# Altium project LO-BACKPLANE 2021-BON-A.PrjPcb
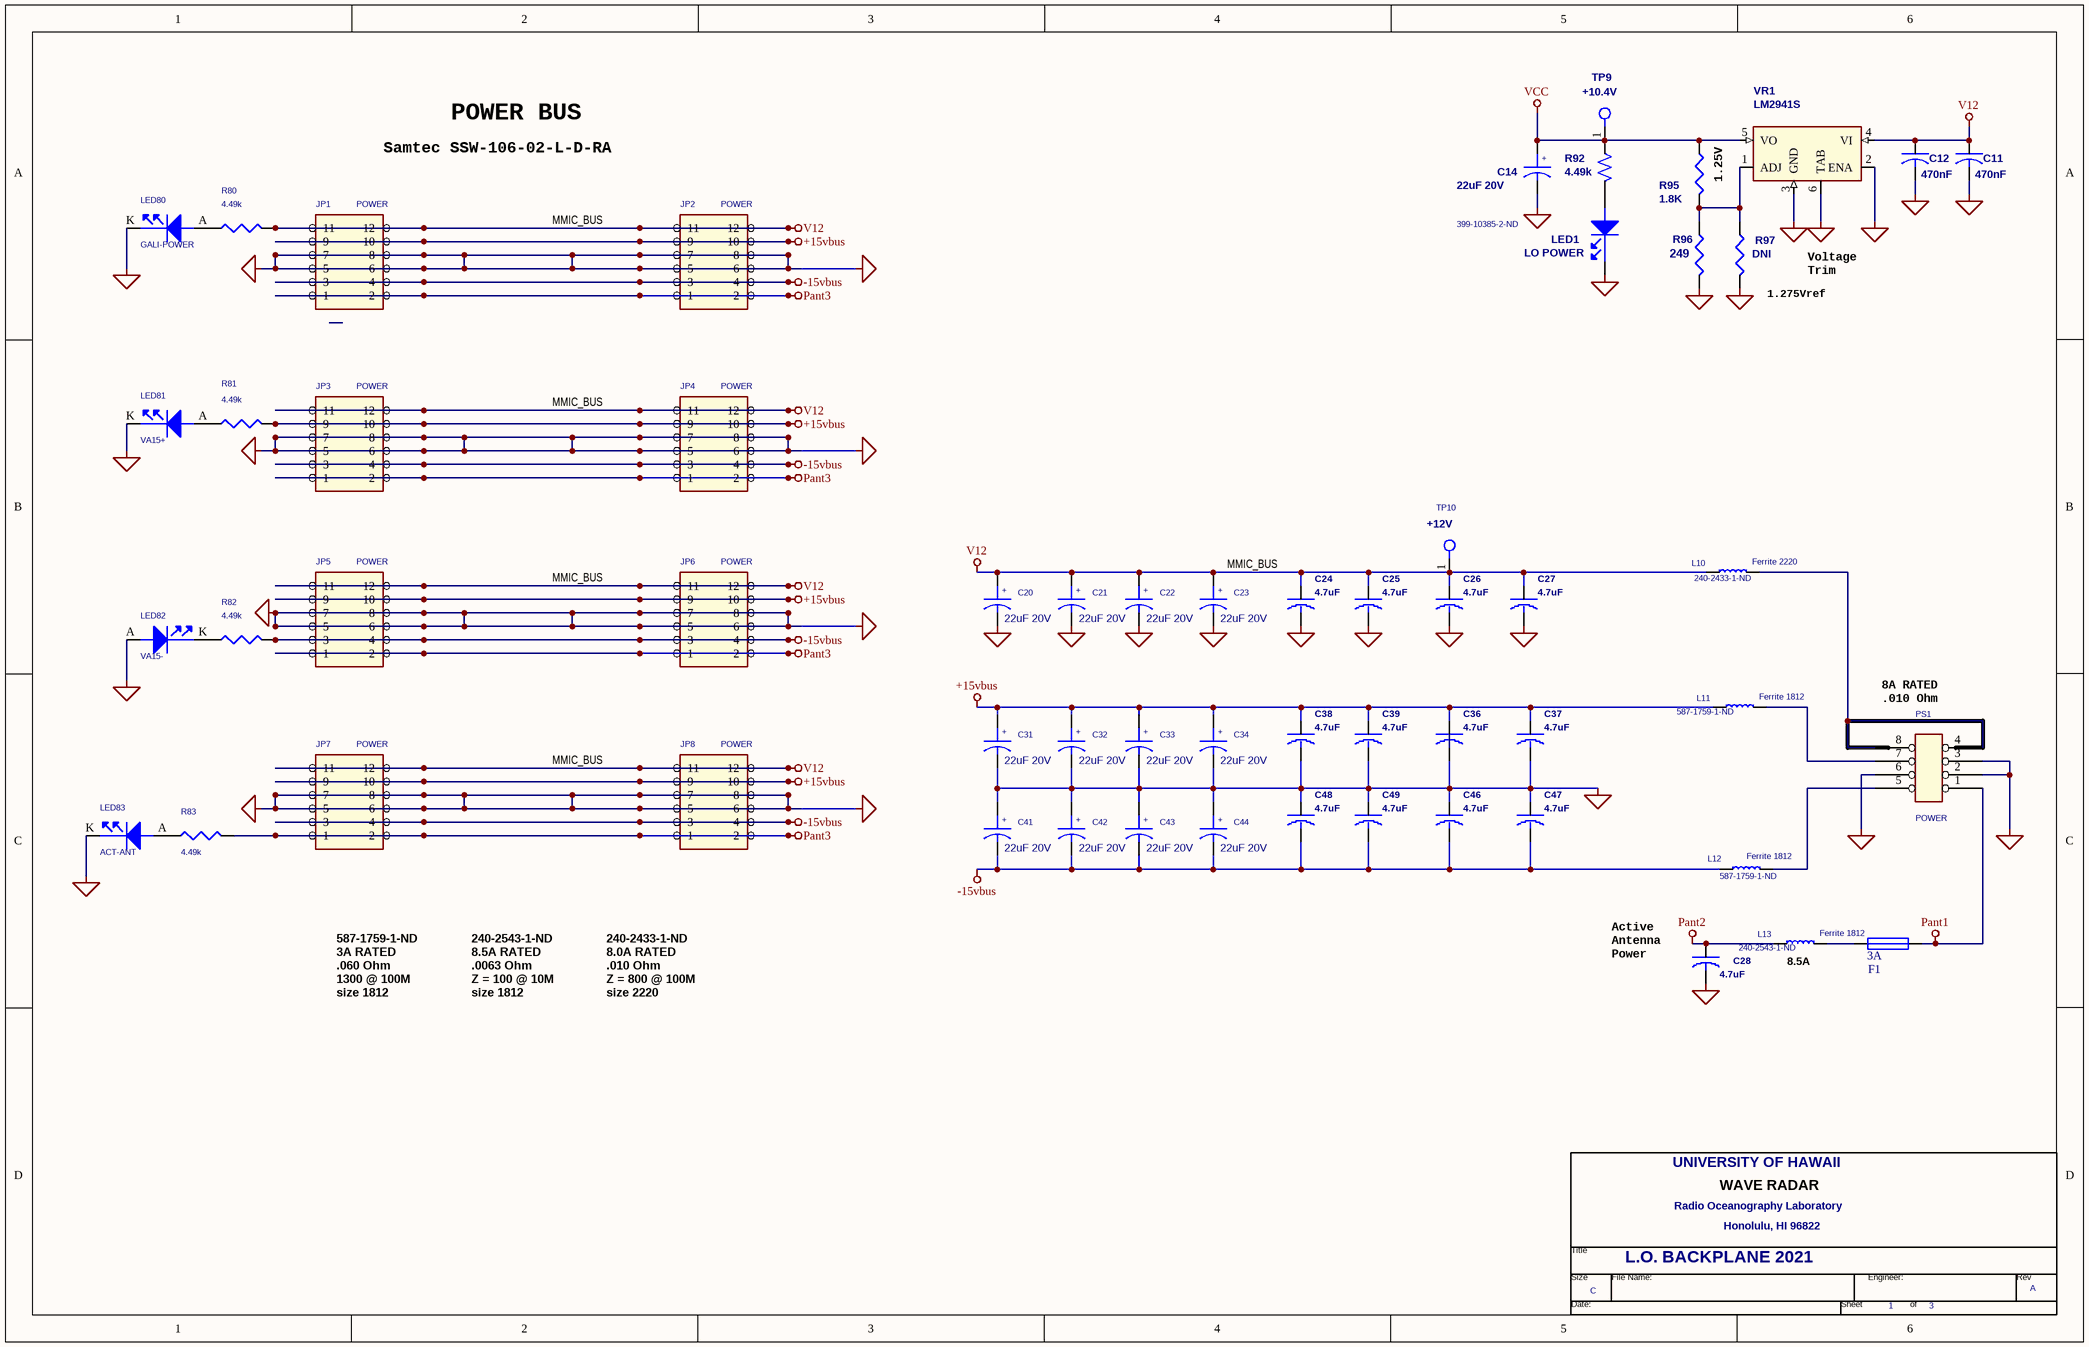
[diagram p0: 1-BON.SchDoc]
3 sheets, 162 parts. Net scope: global (net labels, ports and power ports of the same name join across sheets).
Board file: LO-BACKPLANE2021-BON.PcbDoc
Sheets:
  1-BON.SchDoc
  2-BON.SchDoc
  3-BON.SchDoc

## Sheet 1-BON.SchDoc
size OrCAD B; Organization: Altium Limited; Address1: L3, 12a Rodborough Rd; Address2: Frenchs Forest; Address3: NSW; Address4: Australia 2086

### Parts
(Parts that share a designator on the sheet are numbered #1, #2 ... from top to bottom, then left to right.)
*#1  Page Count: 3  Page Number: 1  Page Size: C  OrgAddr3: Honolulu, HI 96822  OrgAddr1: Radio Oceanography Laboratory  OrgName: UNIVERSITY OF HAWAII  Title: L.O. BACKPLANE 2021  RevCode: A  (hidden comment: HWRadar)  (graphical)
C11  470nF  [0612]
C12  470nF  [0612]
C14  22uF 20V  DK Stock: 399-10385-2-ND  [293D]
C20  22uF 20V  [293D]
C21  22uF 20V  [293D]
C22  22uF 20V  [293D]
C23  22uF 20V  [293D]
C24  4.7uF  [1210]
C25  4.7uF  [1210]
C26  4.7uF  [1210]
C27  4.7uF  [1210]
C28  4.7uF  [1210]
C31  22uF 20V  [293D]
C32  22uF 20V  [293D]
C33  22uF 20V  [293D]
C34  22uF 20V  [293D]
C36  4.7uF  [1210]
C37  4.7uF  [1210]
C38  4.7uF  [1210]
C39  4.7uF  [1210]
C41  22uF 20V  [293D]
C42  22uF 20V  [293D]
C43  22uF 20V  [293D]
C44  22uF 20V  [293D]
C46  4.7uF  [1210]
C47  4.7uF  [1210]
C48  4.7uF  [1210]
C49  4.7uF  [1210]
F1  3A  [0452 (Littlefuse)]
JP1  POWER  [SSW-106-02-G-D-RA]
JP2  POWER  [SSW-106-02-G-D-RA]
JP3  POWER  [SSW-106-02-G-D-RA]
JP4  POWER  [SSW-106-02-G-D-RA]
JP5  POWER  [SSW-106-02-G-D-RA]
JP6  POWER  [SSW-106-02-G-D-RA]
JP7  POWER  [SSW-106-02-G-D-RA]
JP8  POWER  [SSW-106-02-G-D-RA]
L10  Ferrite 2220  DK Stock: 240-2433-1-ND  [2220]
L11  Ferrite 1812  DK Stock: 587-1759-1-ND  [1812]
L12  Ferrite 1812  DK Stock: 587-1759-1-ND  [1812]
L13  Ferrite 1812  DK Stock: 240-2543-1-ND  [1812]
LED1  LO POWER  [1206D1]
LED80  GALI-POWER  [1206D1]
LED81  VA15+  [1206D1]
LED82  VA15-  [1206D1]
LED83  ACT-ANT  [1206D1]
PS1  POWER  [MFTJR2X4]
R80  4.49k  [R1206]
R81  4.49k  [R1206]
R82  4.49k  [R1206]
R83  4.49k  [R1206]
R92  4.49k  [R1206]
R95  1.8K  [R1206]
R96  249  [R1206]
R97  DNI  [R1206]
TP9  +10.4V  [61300111121]
TP10  +12V  [61300111121]
VR1  LM2941S  [TO263-5]

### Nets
+15vbus: C31.+ C32.+ C33.+ C34.+ C36.1 C37.1 C38.1 C39.1 JP1.9 JP1.10 JP2.9 JP2.10 JP3.9 JP3.10 JP4.9 JP4.10 JP5.9 JP5.10 JP6.9 JP6.10 JP7.9 JP7.10 JP8.9 JP8.10 L11.1 R81.2
-15vbus: C41.- C42.- C43.- C44.- C46.2 C47.2 C48.2 C49.2 JP1.3 JP1.4 JP2.3 JP2.4 JP3.3 JP3.4 JP4.3 JP4.4 JP5.3 JP5.4 JP6.3 JP6.4 JP7.3 JP7.4 JP8.3 JP8.4 L12.1 R82.2
GND: C11.2 C12.2 C14.- C20.- C21.- C22.- C23.- C24.2 C25.2 C26.2 C27.2 C28.2 C31.- C32.- C33.- C34.- C36.2 C37.2 C38.2 C39.2 C41.+ C42.+ C43.+ C44.+ C46.1 C47.1 C48.1 C49.1 JP1.5 JP1.6 JP1.7 JP1.8 JP2.5 JP2.6 JP2.7 JP2.8 JP3.5 JP3.6 JP3.7 JP3.8 JP4.5 JP4.6 JP4.7 JP4.8 JP5.5 JP5.6 JP5.7 JP5.8 JP6.5 JP6.6 JP6.7 JP6.8 JP7.5 JP7.6 JP7.7 JP7.8 JP8.5 JP8.6 JP8.7 JP8.8 LED1.K(CATHODE) LED80.K(CATHODE) LED81.K(CATHODE) LED82.A(ANODE) LED83.K(CATHODE) PS1.2 PS1.3 PS1.6 R96.2 R97.2 VR1.2(ENA) VR1.3(GND) VR1.6(TAB)
Pant1: F1.2 PS1.1
Pant2: C28.1 L13.1
Pant3: JP1.1 JP1.2 JP2.1 JP2.2 JP3.1 JP3.2 JP4.1 JP4.2 JP5.1 JP5.2 JP6.1 JP6.2 JP7.1 JP7.2 JP8.1 JP8.2 R83.2
V12: C11.1 C12.1 C20.+ C21.+ C22.+ C23.+ C24.1 C25.1 C26.1 C27.1 JP1.11 JP1.12 JP2.11 JP2.12 JP3.11 JP3.12 JP4.11 JP4.12 JP5.11 JP5.12 JP6.11 JP6.12 JP7.11 JP7.12 JP8.11 JP8.12 L10.1 R80.2 TP10.1(TP) VR1.4(VI)
VCC: C14.+ R92.1 R95.1 TP9.1(TP) VR1.5(VO)
NetF1_1: F1.1 L13.2
NetL10_2: L10.2 PS1.4 PS1.8
NetL11_2: L11.2 PS1.7
NetL12_2: L12.2 PS1.5
NetLED1_A: LED1.A(ANODE) R92.2
NetLED80_A: LED80.A(ANODE) R80.1
NetLED81_A: LED81.A(ANODE) R81.1
NetLED82_K: LED82.K(CATHODE) R82.1
NetLED83_A: LED83.A(ANODE) R83.1
NetR95_2: R95.2 R96.1 R97.1 VR1.1(ADJ)

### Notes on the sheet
- Samtec SSW-106-02-L-D-RA
- POWER BUS
- (near R95) 1.25V
- MMIC_BUS
- Voltage
  Trim
- (near R97) 1.275Vref
- (near C23) MMIC_BUS
- (near PS1) 8A RATED
  .010 Ohm
- (near L13) 8.5A
- 587-1759-1-ND
  3A RATED
  .060 Ohm
  1300 @ 100M
  size 1812
- 240-2543-1-ND
  8.5A RATED
  .0063 Ohm
  Z = 100 @ 10M
  size 1812
- 240-2433-1-ND
  8.0A RATED
  .010 Ohm
  Z = 800 @ 100M
  size 2220
- (near C28) Active
  Antenna
  Power

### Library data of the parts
*#1 = HWRadar: OrgAddr2: 2525 Correa Road; Engineer:: <ENG>
C11 C12 = CAP: MFR PART: C1632X7R1E474M115AC; MFR: TDK; DK Stock: 445-14304-1-ND
C14 = CAPACITOR POL: MFR PART: T495D226M020ATE225; MFR: Kemet
C20-C23 C31-C34 C41-C44 = CAPACITOR POL: MFR PART: T495D226M020ATE225; MFR: Kemet; DK Stock: 399-10385-1-ND
C24-C28 C36-C39 C46-C49 = C1206: MFR PART: C3225X7R1E475K200AA; MFR: TDK Corporation; DK Stock: 445-1433-2-ND
F1 = FUSE1: Fuse
JP1-JP8 = HEADER 6X2: MFR: Samtec Inc.; DK Stock: SAM1215-06-ND
L10 = IND: MFR PART: HR2220V801R-10; MFR: Laird
L11 L12 = IND: MFR PART: FBMH4532HM132-T; MFR: Taiyo Yuden
L13 = IND: MFR PART: HI1812V101R-10; MFR: Laird
LED1 = LED_1: MFR PART: APTL3216CGCK; MFR: Kingbright; DK Stock: 754-1162-1-ND
LED80 = LED_0: MFR PART: APTD3216SURCK; MFR: Kingbright; DK Stock: 754-1159-1-ND
LED81 = LED_0: MFR PART: APTD3216SECK; MFR: Kingbright; DK Stock: 754-1156-1-ND
LED82 = LED_0: MFR PART: APTD3216SYCK; MFR: Kingbright; DK Stock: 754-1160-1-ND
LED83 = LED_0: MFR PART: APTD3216QBC/D; MFR: Kingbright; DK Stock: 754-1442-1-ND
PS1 = HEADER 4X2_0: MFR PART: 0039281083; MFR: M olex; DK Stock: WM3803-ND
R80-R83 = RESISTOR: MFR PART: RC1206FR-072K49L; MFR: Yageo; DK Stock: 311-2.49KFRCT-ND
R92 = RES1206: MFR PART: RC1206FR-072K49L; MFR: Yageo; DK Stock: 311-4.99KFRCT-ND
R95 = RESISTOR: MFR PART: RC1206FR-071K8L; MFR: Yageo; DK Stock: 311-1.80kFRCT-ND
R96 = RESISTOR: MFR PART: RC1206FR-07249RL; MFR: Yageo; DK Stock: 311-249FRCT-ND
R97 = RESISTOR: MFR PART: ns; DK Stock: OMIT
TP9 = TP_0: MFR PART: ns; DK Stock: n/s
TP10 = TP_0: DK Stock: n/s
VR1 = LM7805_0: MFR PART: LM2941SX; MFR: TI; DK Stock: LM2941SXCT-ND

## Sheet 2-BON.SchDoc
size OrCAD B; Organization: Altium Limited; Address1: L3, 12a Rodborough Rd; Address2: Frenchs Forest; Address3: NSW; Address4: Australia 2086
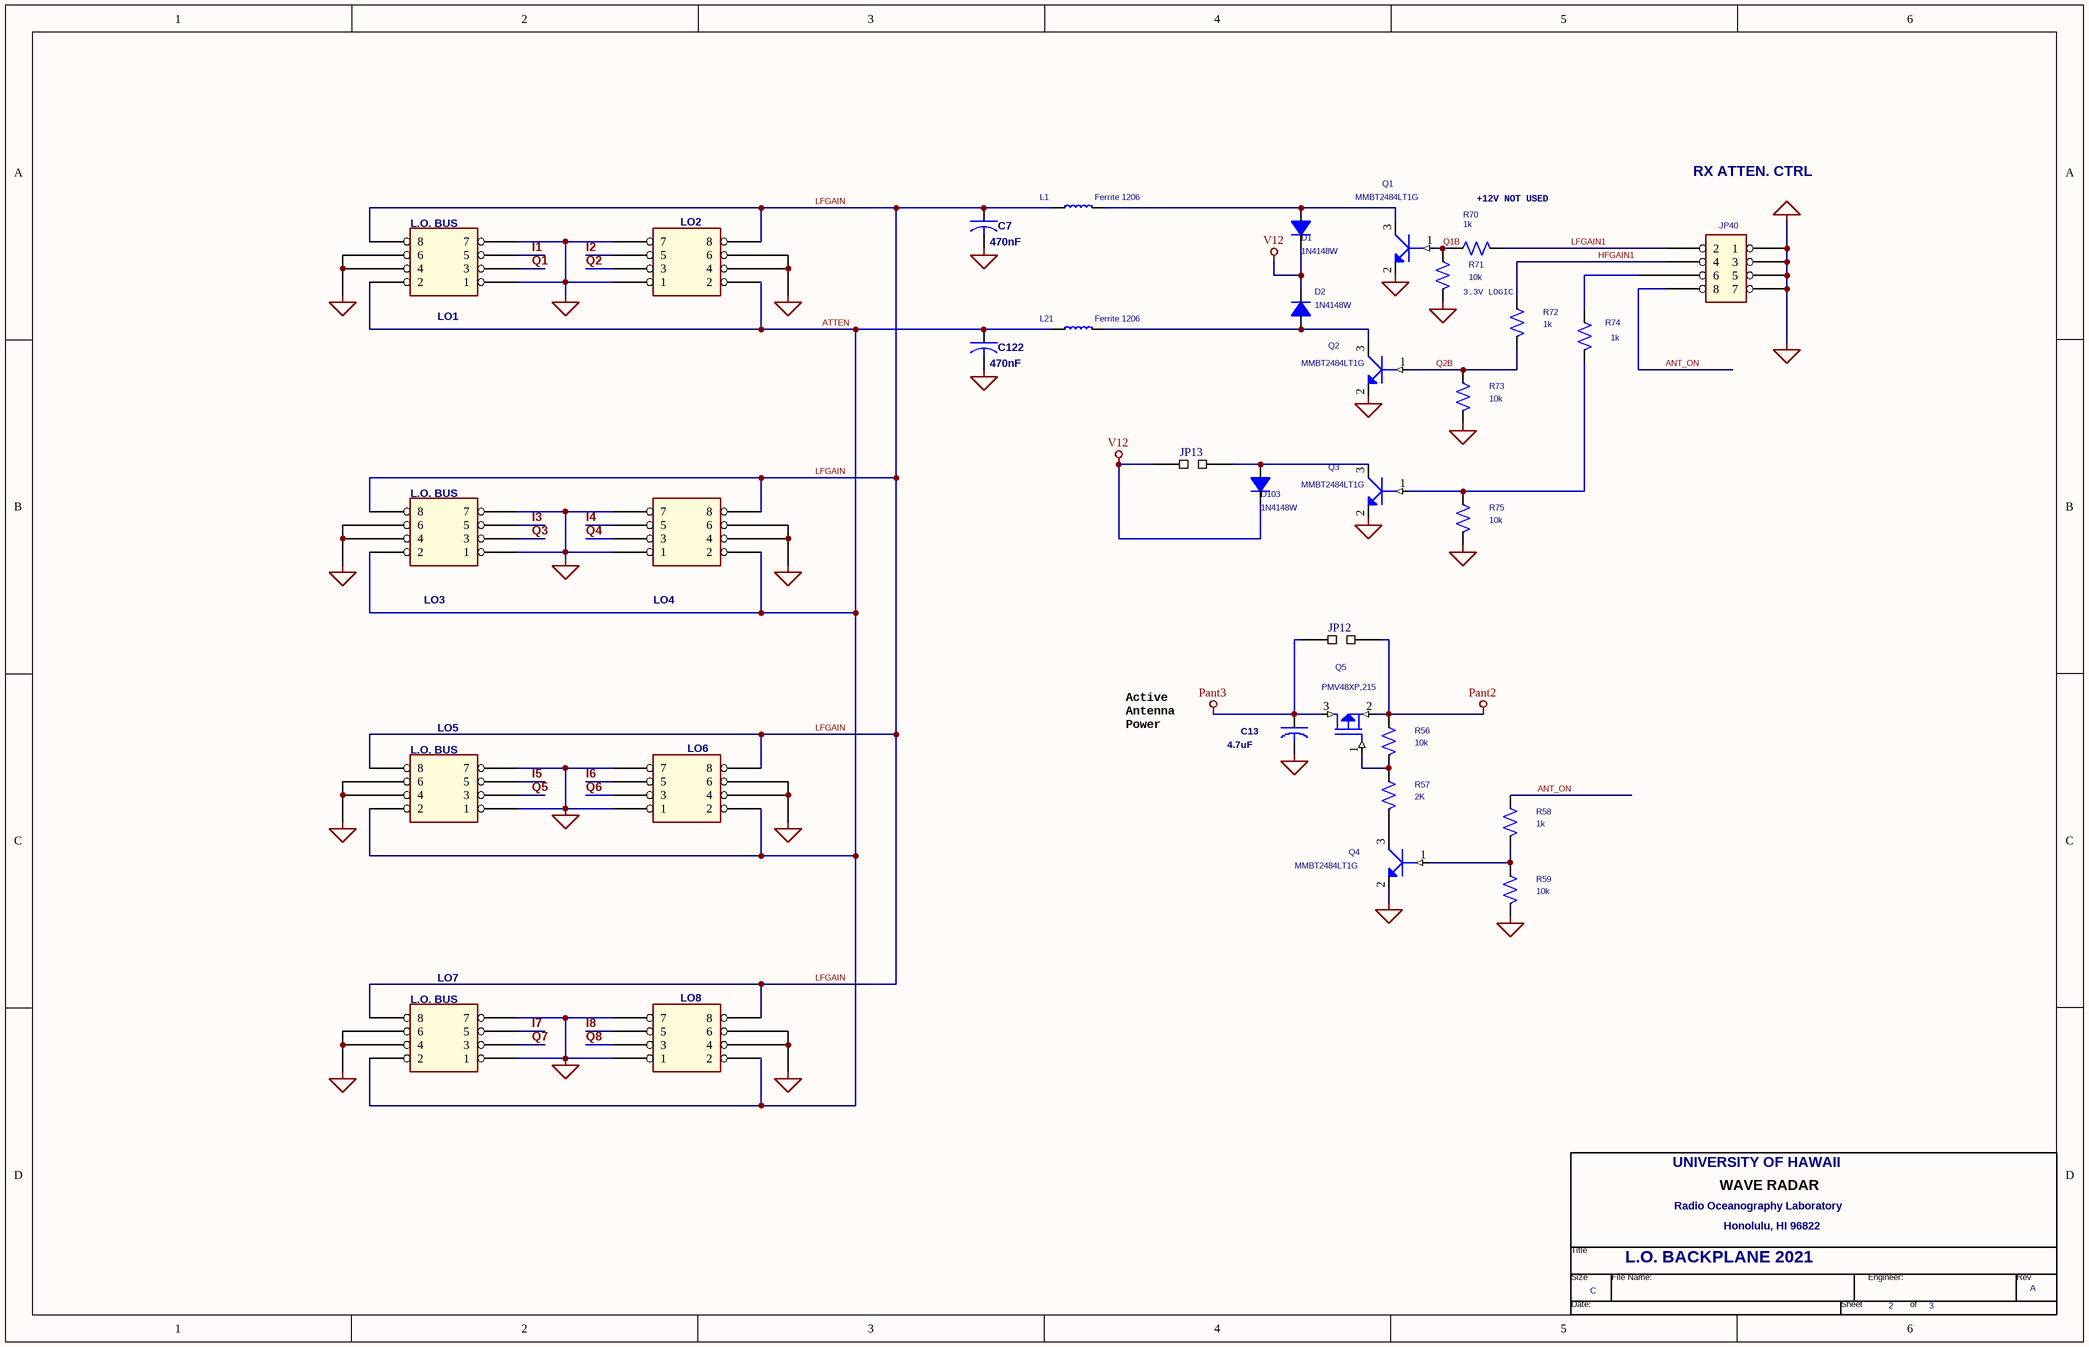
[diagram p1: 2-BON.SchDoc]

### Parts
(Parts that share a designator on the sheet are numbered #1, #2 ... from top to bottom, then left to right.)
*#2  Page Count: 3  Page Number: 2  Page Size: C  OrgAddr3: Honolulu, HI 96822  OrgAddr1: Radio Oceanography Laboratory  OrgName: UNIVERSITY OF HAWAII  Title: L.O. BACKPLANE 2021  RevCode: A  (hidden comment: HWRadar)  (graphical)
C7  470nF  [0612]
C13  4.7uF  [1206]
C122  470nF  [0612]
D1  1N4148W  [SOD123]
D2  1N4148W  [SOD123]
D103  1N4148W  [SOD123]
JP12  (no value)  [2X2.54]
JP13  (no value)  [2X2.54]
JP40  RX ATTEN. CTRL  [2MM4X2SHRD]
L1  Ferrite 1206  [1206]
L21  Ferrite 1206  [1206]
LO1  L.O. BUS  [SSW-104-02-G-D-RA]
LO2  L.O. BUS  [SSW-104-02-G-D-RA]  (value not drawn)
LO3  L.O. BUS  [SSW-104-02-G-D-RA]
LO4  L.O. BUS  [SSW-104-02-G-D-RA]  (value not drawn)
LO5  L.O. BUS  [SSW-104-02-G-D-RA]
LO6  L.O. BUS  [SSW-104-02-G-D-RA]  (value not drawn)
LO7  L.O. BUS  [SSW-104-02-G-D-RA]
LO8  L.O. BUS  [SSW-104-02-G-D-RA]  (value not drawn)
Q1  MMBT2484LT1G  [SOT23]
Q2  MMBT2484LT1G  [SOT23]
Q3  MMBT2484LT1G  [SOT23]
Q4  MMBT2484LT1G  [SOT23]
Q5  PMV48XP,215  [SOT23]
R56  10k  [1206]
R57  2K  [1206]
R58  1k  [1206]
R59  10k  [1206]
R70  1k  [1206]
R71  10k  [1206]
R72  1k  [1206]
R73  10k  [1206]
R74  1k  [1206]
R75  10k  [1206]

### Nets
GND: C7.2 C13.2 C122.2 JP40.1 JP40.3 JP40.5 JP40.7 LO1.1 LO1.4 LO1.6 LO1.7 LO2.1 LO2.4 LO2.6 LO2.7 LO3.1 LO3.4 LO3.6 LO3.7 LO4.1 LO4.4 LO4.6 LO4.7 LO5.1 LO5.4 LO5.6 LO5.7 LO6.1 LO6.4 LO6.6 LO6.7 LO7.1 LO7.4 LO7.6 LO7.7 LO8.1 LO8.4 LO8.6 LO8.7 Q1.2(EMITTER) Q2.2(EMITTER) Q3.2(EMITTER) Q4.2(EMITTER) R59.2 R71.2 R73.2 R75.2
Pant2: JP12.2 Q5.2(SOURCE) R56.1
Pant3: C13.1 JP12.1 Q5.3(DRAIN)
V12: D1.K(CATH) D2.K(CATH) D103.K(CATH) JP13.1
ANT_ON: JP40.8 R58.1
ATTEN: C122.1 L21.1 LO1.2 LO2.2 LO3.2 LO4.2 LO5.2 LO6.2 LO7.2 LO8.2
HFGAIN1: JP40.4 R72.1
I1: LO1.5
I2: LO2.5
I3: LO3.5
I4: LO4.5
I5: LO5.5
I6: LO6.5
I7: LO7.5
I8: LO8.5
LFGAIN: C7.1 L1.1 LO1.8 LO2.8 LO3.8 LO4.8 LO5.8 LO6.8 LO7.8 LO8.8
LFGAIN1: JP40.2 R70.2
Q1: LO1.3
Q1B: Q1.1(BASE) R70.1 R71.1
Q2: LO2.3
Q2B: Q2.1(BASE) R72.2 R73.1
Q3: LO3.3
Q4: LO4.3
Q5: LO5.3
Q6: LO6.3
Q7: LO7.3
Q8: LO8.3
NetD1_A: D1.A(ANOD) L1.2 Q1.3(COLLECTOR)
NetD2_A: D2.A(ANOD) L21.2 Q2.3(COLLECTOR)
NetD103_A: D103.A(ANOD) JP13.2 Q3.3(COLLECTOR)
NetJP40_6: JP40.6 R74.1
NetQ3_1: Q3.1(BASE) R74.2 R75.1
NetQ4_1: Q4.1(BASE) R58.2 R59.1
NetQ4_3: Q4.3(COLLECTOR) R57.2
NetQ5_1: Q5.1(GATE) R56.2 R57.1

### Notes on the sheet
- +12V NOT USED
- 3.3V LOGIC
- Active
  Antenna
  Power

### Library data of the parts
*#2 = HWRadar: as *#1 on sheet 1-BON
C7 C122 = CAP: as C11 on sheet 1-BON
C13 = C1206: MFR: Taiyo Yuden; DK Stock: 587-1389-1-ND
D1 D2 D103 = DIODE2: MFR: Micro Commercial; MFR PART: 1N4148W-TP; DK Stock: 1N4148WTPMSCT-ND
JP12 JP13 = STRAP
JP40 = HEADER 4X2_1: MFR: 3M; MFR PART: 159208-6012
L1 L21 = IND: MFR: Taiyo Yuden; MFR PART: HZ1206D102R-10
LO1-LO8 = HEADER 4X2: MFR: Samtec; DK Stock: SAM1045-04-ND
Q1-Q4 = NPN_0: DK Stock: MMBT2484LT1GOSCT-ND
Q5 = MOSFET P_0: DK Stock: 568-7579-1-ND
R56 R57 = RES1206: MFR: Yageo
R58 R59 R70-R75 = RES1206_Dup1: MFR: Yageo

## Sheet 3-BON.SchDoc
size OrCAD B; Organization: Altium Limited; Address1: L3, 12a Rodborough Rd; Address2: Frenchs Forest; Address3: NSW; Address4: Australia 2086
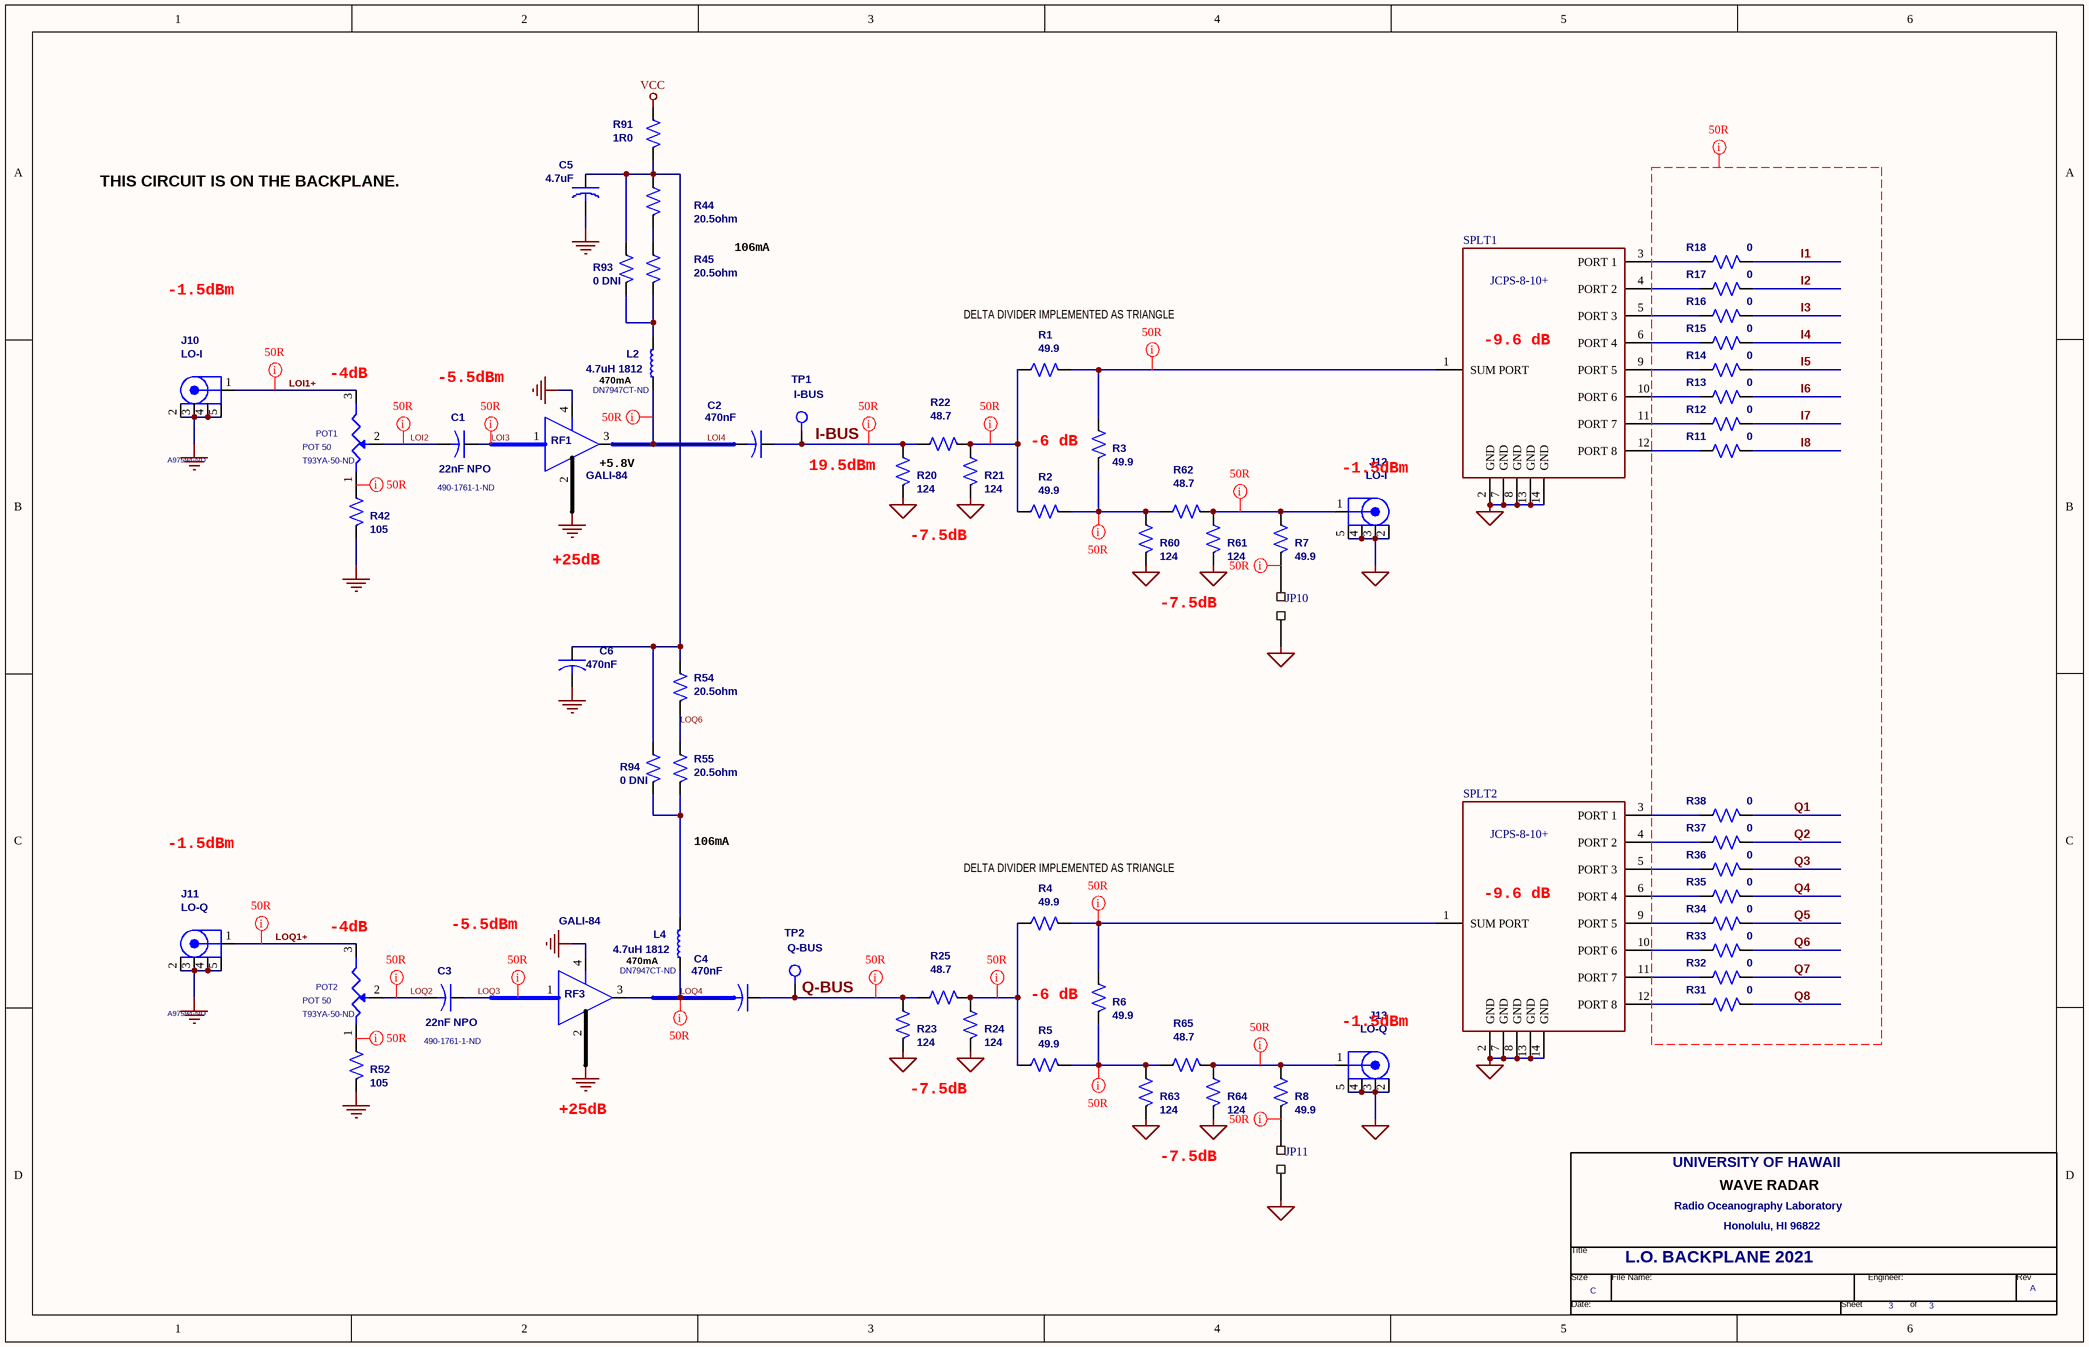
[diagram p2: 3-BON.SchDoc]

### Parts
(Parts that share a designator on the sheet are numbered #1, #2 ... from top to bottom, then left to right.)
*#3  Page Count: 3  Page Size: C  OrgAddr3: Honolulu, HI 96822  OrgAddr1: Radio Oceanography Laboratory  OrgName: UNIVERSITY OF HAWAII  Title: L.O. BACKPLANE 2021  RevCode: A  (hidden comment: HWRadar)  (graphical)
C1  22nF NPO  DK Stock: 490-1761-1-ND  [C1206]
C2  470nF  [0612]
C3  22nF NPO  DK Stock: 490-1761-1-ND  [C1206]
C4  470nF  [0612]
C5  4.7uF  [1210]
C6  470nF  [0612]
J10  LO-I  DK Stock: A97594-ND  [MCX-J-P-H-ST-TH1]
J11  LO-Q  DK Stock: A97594-ND  [MCX-J-P-H-ST-TH1]
J12  LO-I  [MCX-J-P-H-ST-TH1]
J13  LO-Q  [MCX-J-P-H-ST-TH1]
JP10  (no value)  [2X2.54]
JP11  (no value)  [2X2.54]
L2  4.7uH 1812  DK Stock: DN7947CT-ND  [1812]
L4  4.7uH 1812  DK Stock: DN7947CT-ND  [1812]
POT1  POT 50  DK Stock: T93YA-50-ND  [t93ya]
POT2  POT 50  DK Stock: T93YA-50-ND  [t93ya]
R1  49.9  [R1206]
R2  49.9  [R1206]
R3  49.9  [R1206]
R4  49.9  [R1206]
R5  49.9  [R1206]
R6  49.9  [R1206]
R7  49.9  [R1206]
R8  49.9  [R1206]
R11  0  [R1206]
R12  0  [R1206]
R13  0  [R1206]
R14  0  [R1206]
R15  0  [R1206]
R16  0  [R1206]
R17  0  [R1206]
R18  0  [R1206]
R20  124  [R1206]
R21  124  [R1206]
R22  48.7  [R1206]
R23  124  [R1206]
R24  124  [R1206]
R25  48.7  [R1206]
R31  0  [R1206]
R32  0  [R1206]
R33  0  [R1206]
R34  0  [R1206]
R35  0  [R1206]
R36  0  [R1206]
R37  0  [R1206]
R38  0  [R1206]
R42  105  [R1206]
R44  20.5ohm  [2010-5x2.5]
R45  20.5ohm  [2010-5x2.5]
R52  105  [R1206]
R54  20.5ohm  [2010-5x2.5]
R55  20.5ohm  [2010-5x2.5]
R60  124  [R1206]
R61  124  [R1206]
R62  48.7  [R1206]
R63  124  [R1206]
R64  124  [R1206]
R65  48.7  [R1206]
R91  1R0  [R1206]
R93  0 DNI  [R1206]
R94  0 DNI  [R1206]
RF1  GALI-84  [DF782]
RF3  GALI-84  [DF782]
SPLT1  JCPS-8-10+  [BG291]
SPLT2  JCPS-8-10+  [BG291]
TP1  I-BUS  [61300111121]
TP2  Q-BUS  [61300111121]

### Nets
GND: C5.2 C6.2 J10.2(SHIELD) J10.3(SHIELD) J10.4(SHIELD) J10.5(SHIELD) J11.2(SHIELD) J11.3(SHIELD) J11.4(SHIELD) J11.5(SHIELD) J12.2(SHIELD) J12.3(SHIELD) J12.4(SHIELD) J12.5(SHIELD) J13.2(SHIELD) J13.3(SHIELD) J13.4(SHIELD) J13.5(SHIELD) JP10.1 JP11.1 R20.2 R21.2 R23.2 R24.2 R42.2 R52.2 R60.2 R61.2 R63.2 R64.2 RF1.2(GND) RF1.4(GND) RF3.2(GND) RF3.4(GND) SPLT1.2(GND) SPLT1.7(GND) SPLT1.8(GND) SPLT1.13(GND) SPLT1.14(GND) SPLT2.2(GND) SPLT2.7(GND) SPLT2.8(GND) SPLT2.13(GND) SPLT2.14(GND)
VCC: R91.1
I1: R18.2
I2: R17.2
I3: R16.2
I4: R15.2
I5: R14.2
I6: R13.2
I7: R12.2
I8: R11.2
I-BUS: C2.1 R20.1 R22.1 TP1.1(TP)
LOI1+: J10.1(CENTER) POT1.3(B)
LOI2: C1.2 POT1.2(WIPER)
LOI3: C1.1 RF1.1(IN)
LOI4: C2.2 L2.1 RF1.3(OUT)
LOQ1+: J11.1(CENTER) POT2.3(B)
LOQ2: C3.2 POT2.2(WIPER)
LOQ3: C3.1 RF3.1(IN)
LOQ4: C4.2 L4.1 RF3.3(OUT)
LOQ6: R54.2 R55.1
Q1: R38.2
Q2: R37.2
Q3: R36.2
Q4: R35.2
Q5: R34.2
Q6: R33.2
Q7: R32.2
Q8: R31.2
Q-BUS: C4.1 R23.1 R25.1 TP2.1(TP)
NetC5_1: C5.1 C6.1 R44.1 R54.1 R91.2 R93.1 R94.1
NetJ12_1: J12.1(CENTER) R7.1 R61.1 R62.2
NetJ13_1: J13.1(CENTER) R8.1 R64.1 R65.2
NetJP10_2: JP10.2 R7.2
NetJP11_2: JP11.2 R8.2
NetL2_2: L2.2 R45.2 R93.2
NetL4_2: L4.2 R55.2 R94.2
NetPOT1_1: POT1.1(A) R42.1
NetPOT2_1: POT2.1(A) R52.1
NetR1_1: R1.1 R2.1 R21.1 R22.2
NetR1_2: R1.2 R3.1 SPLT1.1(SUM_PORT)
NetR2_2: R2.2 R3.2 R60.1 R62.1
NetR4_1: R4.1 R5.1 R24.1 R25.2
NetR4_2: R4.2 R6.1 SPLT2.1(SUM_PORT)
NetR5_2: R5.2 R6.2 R63.1 R65.1
NetR11_1: R11.1 SPLT1.12(PORT_8)
NetR12_1: R12.1 SPLT1.11(PORT_7)
NetR13_1: R13.1 SPLT1.10(PORT_6)
NetR14_1: R14.1 SPLT1.9(PORT_5)
NetR15_1: R15.1 SPLT1.6(PORT_4)
NetR16_1: R16.1 SPLT1.5(PORT_3)
NetR17_1: R17.1 SPLT1.4(PORT_2)
NetR18_1: R18.1 SPLT1.3(PORT_1)
NetR31_1: R31.1 SPLT2.12(PORT_8)
NetR32_1: R32.1 SPLT2.11(PORT_7)
NetR33_1: R33.1 SPLT2.10(PORT_6)
NetR34_1: R34.1 SPLT2.9(PORT_5)
NetR35_1: R35.1 SPLT2.6(PORT_4)
NetR36_1: R36.1 SPLT2.5(PORT_3)
NetR37_1: R37.1 SPLT2.4(PORT_2)
NetR38_1: R38.1 SPLT2.3(PORT_1)
NetR44_2: R44.2 R45.1

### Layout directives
net class 50R: I1, I2, I3, I4, I5, I6, I7, I8, I-BUS, LOI1+, LOI2, LOI3, LOI4, LOQ1+, LOQ2, LOQ3, LOQ4, NetJ12_1, NetJ13_1, NetJP10_2, NetJP11_2, NetPOT1_1, NetPOT2_1, NetR1_1, NetR1_2, NetR2_2, NetR4_1, NetR4_2, NetR5_2, Q1, Q2, Q3, Q4, Q5, Q6, Q7, Q8, Q-BUS

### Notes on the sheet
- THIS CIRCUIT IS ON THE BACKPLANE.
- 106mA
- -1.5dBm
- (near R1) DELTA DIVIDER IMPLEMENTED AS TRIANGLE
- (near SPLT1) -9.6 dB
- (near POT1) -4dB
- -5.5dBm
- 470mA
- (near RF1) +5.8V
- 19.5dBm
- (near R3) -6 dB
- -7.5dB
- +25dB
- (near R4) DELTA DIVIDER IMPLEMENTED AS TRIANGLE
- (near POT2) -4dB
- (near RF3) 470mA
- (near SPLT2) -9.6 dB
- (near R6) -6 dB

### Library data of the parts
*#3 = HWRadar: as *#1 on sheet 1-BON
C1 C3 = CAP: MFR PART: GRM3195C1H223JA01D; MFR: Murata
C2 C4 C6 = CAP: as C11 on sheet 1-BON
C5 = C1206: MFR PART: C3225X7R1E475K200AA; MFR: TDK; DK Stock: 445-1433-2-ND
J10 J11 = SMA-4G: MFR PART: 5-1814832-1; MFR: TE Connectivity AMP Connectors
J12 J13 = SMA-4G: MFR PART: 5-1814832-1; MFR: TE Connectivity AMP Connectors; DK Stock: A97594-ND
JP10 JP11 = STRAP
L2 L4 = IND: MFR PART: S1812R-472K; MFR: API Delevan
POT1 POT2 = POT: MFR PART: T93YA500KT20; MFR: Vishay Sfernice
R1-R8 R11-R18 R20-R25 R31-R38 R42 R52 R60-R65 = RES: MFR PART: RC1206FR-07105RL; MFR: Yageo; DK Stock: 311-105FRCT-ND
R44 R45 R54 R55 = R1206: MFR PART: CRCW201020R5FKEF; MFR: Vishay Dale; DK Stock: 541-20.5ACCT-ND
R91 = RES1206: MFR PART: RC1206FR-071RL; MFR: Yageo; DK Stock: 311-1.00FRCT-ND
R93 R94 = R1206: MFR: Vishay Dale
RF1 RF3 = GVA-84: MFR: MiniCircuits
TP1 TP2 = TP: MFR PART: ns; DK Stock: n/s

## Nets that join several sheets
GND: 1-BON (73 pins), 2-BON (47 pins), 3-BON (44 pins)
Pant2: 1-BON (C28.1 L13.1), 2-BON (JP12.2 Q5.2 R56.1)
Pant3: 1-BON (17 pins), 2-BON (C13.1 JP12.1 Q5.3)
V12: 1-BON (30 pins), 2-BON (D1.K D2.K D103.K JP13.1)
VCC: 1-BON (5 pins), 3-BON (R91.1)
I1: 2-BON (LO1.5), 3-BON (R18.2)
I2: 2-BON (LO2.5), 3-BON (R17.2)
I3: 2-BON (LO3.5), 3-BON (R16.2)
I4: 2-BON (LO4.5), 3-BON (R15.2)
I5: 2-BON (LO5.5), 3-BON (R14.2)
I6: 2-BON (LO6.5), 3-BON (R13.2)
I7: 2-BON (LO7.5), 3-BON (R12.2)
I8: 2-BON (LO8.5), 3-BON (R11.2)
Q1: 2-BON (LO1.3), 3-BON (R38.2)
Q2: 2-BON (LO2.3), 3-BON (R37.2)
Q3: 2-BON (LO3.3), 3-BON (R36.2)
Q4: 2-BON (LO4.3), 3-BON (R35.2)
Q5: 2-BON (LO5.3), 3-BON (R34.2)
Q6: 2-BON (LO6.3), 3-BON (R33.2)
Q7: 2-BON (LO7.3), 3-BON (R32.2)
Q8: 2-BON (LO8.3), 3-BON (R31.2)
